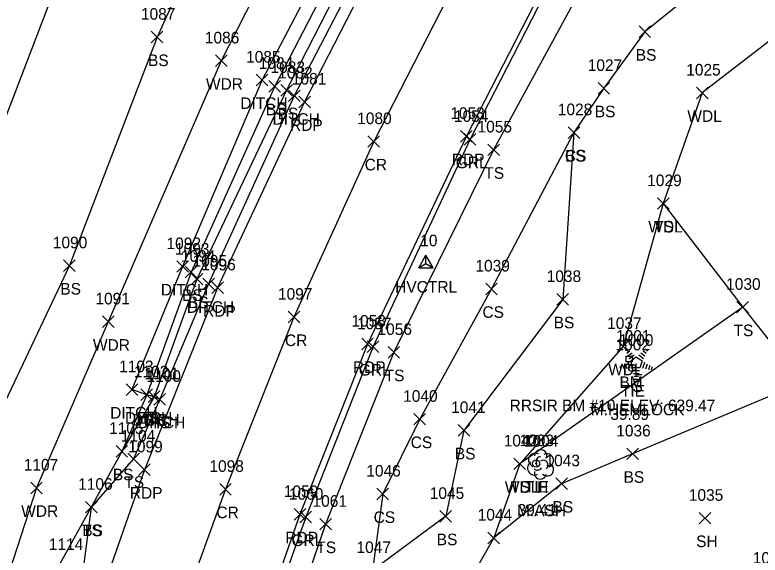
# Model space of a CAD drawing. Extents: x 1551995 to 1555700, y 777276 to 783130.
# Drawn here: x 1554918 to 1555046.7, y 778118.1 to 778211.4 of the extents above; entities that cross this region are included whole.
import ezdxf

# ---------------------------------------------------------------- set-up
doc = ezdxf.new("R2010")
doc.units = 0
for name, color, linetype in [('C_A', 7, 'Continuous'), ('C_C', 7, 'Continuous'), ('C_I', 7, 'Continuous'), ('CBP', 7, 'Continuous'), ('CPBM', 7, 'Continuous'), ('CPSM', 7, 'Continuous'), ('D_A', 7, 'Continuous'), ('D_I', 7, 'Continuous'), ('D_TIC', 7, 'Continuous'), ('DD', 7, 'Continuous'), ('L_A', 7, 'Continuous'), ('L_C', 7, 'Continuous'), ('L_I', 7, 'Continuous'), ('L_TIC', 7, 'Continuous'), ('LAWA', 7, 'Continuous'), ('LELB', 7, 'Continuous'), ('LTC', 7, 'Continuous'), ('LTD', 7, 'Continuous'), ('P_A', 7, 'Continuous'), ('P_I', 7, 'Continuous'), ('P_TIC', 7, 'Continuous'), ('PET', 7, 'Continuous'), ('PRC', 7, 'Continuous'), ('R_A', 7, 'Continuous'), ('R_I', 7, 'Continuous'), ('R_TIC', 7, 'Continuous'), ('RGR', 7, 'Continuous')]:
    doc.layers.add(name, color=color, linetype=linetype)

msp = doc.modelspace()

# ---------------------------------------------------------------- linework, layer by layer
at = {"layer": 'CBP'}
for centre, radius in [((1555024.62, 778150.43), 0.625), ((1555024.62, 778150.43), 0.0833), ((1555008.03, 778133.9), 0.625), ((1555008.03, 778133.9), 0.0833)]:
    msp.add_circle(centre, radius, dxfattribs=at)
at = {"layer": 'CPBM'}
for p, q in [((1555023.63, 778151.43), (1555023.63, 778152.43)), ((1555023.63, 778152.43), (1555024.63, 778152.43)), ((1555024.63, 778151.43), (1555023.63, 778151.43)), ((1555024.13, 778151.93), (1555024.13, 778151.93)), ((1555024.13, 778151.93), (1555024.13, 778151.93)), ((1555024.63, 778152.43), (1555024.63, 778151.43))]:
    msp.add_line(p, q, dxfattribs=at)
at = {"layer": 'CPSM'}
for p, q in [((1554987.76, 778167.69), (1554989.01, 778169.86)), ((1554987.76, 778167.69), (1554989.01, 778169.86)), ((1554987.76, 778167.69), (1554989.01, 778169.86)), ((1554987.76, 778167.69), (1554989.01, 778169.86)), ((1554987.76, 778167.69), (1554989.01, 778169.86)), ((1554987.76, 778167.69), (1554989.01, 778169.86)), ((1554987.76, 778167.69), (1554989.01, 778169.86)), ((1554990.26, 778167.69), (1554989.01, 778169.86)), ((1554989.01, 778168.41), (1554989.01, 778169.86)), ((1554990.26, 778167.69), (1554989.01, 778169.86)), ((1554989.01, 778168.41), (1554989.01, 778169.86)), ((1554990.26, 778167.69), (1554989.01, 778169.86)), ((1554989.01, 778168.41), (1554989.01, 778169.86)), ((1554990.26, 778167.69), (1554989.01, 778169.86)), ((1554989.01, 778168.41), (1554989.01, 778169.86)), ((1554990.26, 778167.69), (1554989.01, 778169.86)), ((1554989.01, 778168.41), (1554989.01, 778169.86)), ((1554990.26, 778167.69), (1554989.01, 778169.86)), ((1554989.01, 778168.41), (1554989.01, 778169.86)), ((1554990.26, 778167.69), (1554989.01, 778169.86)), ((1554989.01, 778168.41), (1554989.01, 778169.86)), ((1554987.76, 778167.69), (1554989.01, 778168.41)), ((1554987.76, 778167.69), (1554989.01, 778168.41)), ((1554987.76, 778167.69), (1554989.01, 778168.41)), ((1554987.76, 778167.69), (1554989.01, 778168.41)), ((1554987.76, 778167.69), (1554989.01, 778168.41)), ((1554987.76, 778167.69), (1554989.01, 778168.41)), ((1554987.76, 778167.69), (1554989.01, 778168.41)), ((1554989.01, 778168.41), (1554989.01, 778168.41)), ((1554989.01, 778168.41), (1554990.26, 778167.69)), ((1554989.01, 778168.41), (1554989.01, 778168.41)), ((1554989.01, 778168.41), (1554990.26, 778167.69)), ((1554989.01, 778168.41), (1554989.01, 778168.41)), ((1554989.01, 778168.41), (1554990.26, 778167.69)), ((1554989.01, 778168.41), (1554989.01, 778168.41)), ((1554989.01, 778168.41), (1554990.26, 778167.69)), ((1554989.01, 778168.41), (1554989.01, 778168.41)), ((1554989.01, 778168.41), (1554990.26, 778167.69)), ((1554989.01, 778168.41), (1554989.01, 778168.41)), ((1554989.01, 778168.41), (1554990.26, 778167.69)), ((1554989.01, 778168.41), (1554989.01, 778168.41)), ((1554989.01, 778168.41), (1554990.26, 778167.69)), ((1554987.76, 778167.69), (1554990.26, 778167.69)), ((1554987.76, 778167.69), (1554990.26, 778167.69)), ((1554987.76, 778167.69), (1554990.26, 778167.69)), ((1554987.76, 778167.69), (1554990.26, 778167.69)), ((1554987.76, 778167.69), (1554990.26, 778167.69)), ((1554987.76, 778167.69), (1554990.26, 778167.69)), ((1554987.76, 778167.69), (1554990.26, 778167.69))]:
    msp.add_line(p, q, dxfattribs=at)
at = {"layer": 'D_TIC'}
for points in [[(1554959.71, 778199.12), (1554961.71, 778201.12)], [(1554961.71, 778199.12), (1554959.71, 778201.12)], [(1554965.26, 778196.38), (1554967.26, 778198.38)], [(1554967.26, 778196.38), (1554965.26, 778198.38)], [(1554945.97, 778166.91), (1554947.97, 778168.91)], [(1554947.97, 778166.91), (1554945.97, 778168.91)], [(1554950.47, 778163.91), (1554952.47, 778165.91)], [(1554952.47, 778163.91), (1554950.47, 778165.91)], [(1554937.22, 778145.67), (1554939.22, 778147.67)], [(1554939.22, 778145.67), (1554937.22, 778147.67)], [(1554937.22, 778145.67), (1554939.22, 778147.67)], [(1554939.22, 778145.67), (1554937.22, 778147.67)], [(1554939.77, 778144.78), (1554941.77, 778146.78)], [(1554941.77, 778144.78), (1554939.77, 778146.78)], [(1554941.04, 778144.43), (1554943.04, 778146.43)], [(1554943.04, 778144.43), (1554941.04, 778146.43)], [(1554942.03, 778144), (1554944.03, 778146)], [(1554944.03, 778144), (1554942.03, 778146)]]:
    msp.add_lwpolyline(points, dxfattribs=at)
at = {"layer": 'DD'}
for points in [[(1555007.77, 778290.58), (1554983.94, 778244.46), (1554960.71, 778200.12), (1554946.97, 778167.91), (1554938.22, 778146.67)], [(1555014.72, 778285.98), (1554988.93, 778241.04), (1554966.26, 778197.38), (1554951.47, 778164.91), (1554943.03, 778145), (1554942.04, 778145.43), (1554940.77, 778145.78), (1554938.22, 778146.67)]]:
    msp.add_lwpolyline(points, dxfattribs=at)
at = {"layer": 'L_TIC'}
for points in [[(1555025.82, 778207.44), (1555027.82, 778209.44)], [(1555027.82, 778207.44), (1555025.82, 778209.44)], [(1554941.56, 778206.52), (1554943.56, 778208.52)], [(1554943.56, 778206.52), (1554941.56, 778208.52)], [(1554952.65, 778202.43), (1554954.65, 778204.43)], [(1554954.65, 778202.43), (1554952.65, 778204.43)], [(1554961.9, 778198.03), (1554963.9, 778200.03)], [(1554963.9, 778198.03), (1554961.9, 778200.03)], [(1554963.94, 778197.34), (1554965.94, 778199.34)], [(1554965.94, 778197.34), (1554963.94, 778199.34)], [(1555018.74, 778197.68), (1555020.74, 778199.68)], [(1555020.74, 778197.68), (1555018.74, 778199.68)], [(1555035.75, 778196.89), (1555037.75, 778198.89)], [(1555037.75, 778196.89), (1555035.75, 778198.89)], [(1555013.58, 778190.04), (1555015.58, 778192.04)], [(1555015.58, 778190.04), (1555013.58, 778192.04)], [(1555013.58, 778190.04), (1555015.58, 778192.04)], [(1555015.58, 778190.04), (1555013.58, 778192.04)], [(1554999.7, 778187.06), (1555001.7, 778189.06)], [(1555001.7, 778187.06), (1554999.7, 778189.06)], [(1555029.02, 778177.79), (1555031.02, 778179.79)], [(1555031.02, 778177.79), (1555029.02, 778179.79)], [(1555029.02, 778177.79), (1555031.02, 778179.79)], [(1555031.02, 778177.79), (1555029.02, 778179.79)], [(1554926.41, 778167.06), (1554928.41, 778169.06)], [(1554928.41, 778167.06), (1554926.41, 778169.06)], [(1554947.43, 778165.96), (1554949.43, 778167.96)], [(1554949.43, 778165.96), (1554947.43, 778167.96)], [(1554948.46, 778164.73), (1554950.46, 778166.73)], [(1554950.46, 778164.73), (1554948.46, 778166.73)], [(1554999.34, 778163.05), (1555001.34, 778165.05)], [(1555001.34, 778163.05), (1554999.34, 778165.05)], [(1555011.64, 778161.24), (1555013.64, 778163.24)], [(1555013.64, 778161.24), (1555011.64, 778163.24)], [(1555042.74, 778159.89), (1555044.74, 778161.89)], [(1555044.74, 778159.89), (1555042.74, 778161.89)], [(1555042.74, 778159.89), (1555044.74, 778161.89)], [(1555044.74, 778159.89), (1555042.74, 778161.89)], [(1554933.13, 778157.37), (1554935.13, 778159.37)], [(1554935.13, 778157.37), (1554933.13, 778159.37)], [(1554982.47, 778152.1), (1554984.47, 778154.1)], [(1554984.47, 778152.1), (1554982.47, 778154.1)], [(1555022.09, 778153.13), (1555024.09, 778155.13)], [(1555024.09, 778153.13), (1555022.09, 778155.13)], [(1554939.77, 778144.78), (1554941.77, 778146.78)], [(1554941.77, 778144.78), (1554939.77, 778146.78)], [(1554941.04, 778144.43), (1554943.04, 778146.43)], [(1554943.04, 778144.43), (1554941.04, 778146.43)], [(1554942.03, 778144), (1554944.03, 778146)], [(1554944.03, 778144), (1554942.03, 778146)], [(1554986.94, 778140.56), (1554988.94, 778142.56)], [(1554988.94, 778140.56), (1554986.94, 778142.56)], [(1554994.57, 778138.61), (1554996.57, 778140.61)], [(1554996.57, 778138.61), (1554994.57, 778140.61)], [(1554935.48, 778135), (1554937.48, 778137)], [(1554937.48, 778135), (1554935.48, 778137)], [(1554935.48, 778135), (1554937.48, 778137)], [(1554937.48, 778135), (1554935.48, 778137)], [(1555023.71, 778134.57), (1555025.71, 778136.57)], [(1555025.71, 778134.57), (1555023.71, 778136.57)], [(1554937.52, 778133.69), (1554939.52, 778135.69)], [(1554939.52, 778133.69), (1554937.52, 778135.69)], [(1555004.22, 778132.85), (1555006.22, 778134.85)], [(1555006.22, 778132.85), (1555004.22, 778134.85)], [(1555004.22, 778132.85), (1555006.22, 778134.85)], [(1555006.22, 778132.85), (1555004.22, 778134.85)], [(1554920.74, 778128.69), (1554922.74, 778130.69)], [(1554922.74, 778128.69), (1554920.74, 778130.69)], [(1555011.44, 778129.42), (1555013.44, 778131.42)], [(1555013.44, 778129.42), (1555011.44, 778131.42)], [(1554980.54, 778127.64), (1554982.54, 778129.64)], [(1554982.54, 778127.64), (1554980.54, 778129.64)], [(1554930.2, 778125.36), (1554932.2, 778127.36)], [(1554932.2, 778125.36), (1554930.2, 778127.36)], [(1554930.2, 778125.36), (1554932.2, 778127.36)], [(1554932.2, 778125.36), (1554930.2, 778127.36)], [(1554991.44, 778123.79), (1554993.44, 778125.79)], [(1554993.44, 778123.79), (1554991.44, 778125.79)], [(1554970.68, 778122.43), (1554972.68, 778124.43)], [(1554972.68, 778122.43), (1554970.68, 778124.43)], [(1555036.21, 778123.47), (1555038.21, 778125.47)], [(1555038.21, 778123.47), (1555036.21, 778125.47)], [(1554999.72, 778120.06), (1555001.72, 778122.06)], [(1555001.72, 778120.06), (1554999.72, 778122.06)], [(1554999.72, 778120.06), (1555001.72, 778122.06)], [(1555001.72, 778120.06), (1554999.72, 778122.06)]]:
    msp.add_lwpolyline(points, dxfattribs=at)
at = {"layer": 'LAWA'}
for points in [[(1555000.96, 778294.87), (1554977.33, 778249.83), (1554953.65, 778203.43), (1554934.13, 778158.37), (1554921.74, 778129.69), (1554915, 778109.12), (1554905.48, 778082.18), (1554899.62, 778064.01), (1554889.87, 778042.09), (1554882.71, 778000.01), (1554871.69, 777971.47), (1554868.37, 777961.54), (1554861.96, 777920.45), (1554858.53, 777878.75), (1554855.37, 777850.35), (1554848.67, 777827.4), (1554836.72, 777779.63)], [(1555085.12, 778246.6), (1555062.11, 778217.51), (1555036.75, 778197.89), (1555030.02, 778178.79), (1555023.09, 778154.13), (1555005.22, 778133.85), (1555000.72, 778121.06), (1554983.85, 778091.44), (1554975.19, 778092.03), (1554970.99, 778074.93), (1554967.22, 778059.88), (1554967.17, 778023.98), (1554956.28, 777979.25), (1554949.24, 777950.5), (1554942.15, 777917.97), (1554937.88, 777884.35), (1554924.17, 777845.95), (1554911.99, 777797.39)]]:
    msp.add_lwpolyline(points, dxfattribs=at)
at = {"layer": 'LELB'}
for points in [[(1554968.28, 778312.04), (1554950, 778266.53), (1554926.49, 778220.19), (1554908.96, 778174.42), (1554896.48, 778148.26), (1554883.58, 778119.09), (1554877.33, 778100.58), (1554861.43, 778063.06), (1554849.04, 778068.43), (1554838.51, 778079.97)], [(1554991.44, 778299.23), (1554965.18, 778257.46), (1554942.56, 778207.52), (1554927.41, 778168.06), (1554913.27, 778138.26), (1554902.03, 778109.91)], [(1555010.39, 778288.8), (1554986.01, 778243.63), (1554962.9, 778199.03), (1554948.43, 778166.96), (1554940.77, 778145.78), (1554936.48, 778136)], [(1555012.41, 778287.51), (1554987.42, 778242.35), (1554964.94, 778198.34), (1554949.46, 778165.73), (1554942.04, 778145.43), (1554936.48, 778136), (1554931.2, 778126.36), (1554925.41, 778115.96), (1554925.69, 778108.05), (1554919.03, 778090.31), (1554918.44, 778089.95), (1554914.24, 778077.2), (1554901.57, 778039.07), (1554894.39, 777997.12), (1554883.88, 777962.74), (1554876.08, 777918.21), (1554866.8, 777876.47), (1554857.76, 777827.38), (1554846.36, 777775.83)], [(1555043.36, 778265.96), (1555018.33, 778220.45), (1555000.7, 778188.06), (1554983.47, 778153.1), (1554971.68, 778123.43), (1554963.77, 778100.46)], [(1555062.53, 778257.03), (1555043.05, 778221.53), (1555026.82, 778208.44), (1555019.74, 778198.68), (1555014.58, 778191.04), (1555012.64, 778162.24), (1554995.57, 778139.61), (1554992.44, 778124.79), (1554979.79, 778115.45), (1554974.95, 778099.31), (1554975.19, 778092.03)], [(1555014.58, 778191.04), (1555000.34, 778164.05), (1554987.94, 778141.56), (1554981.54, 778128.64), (1554979.79, 778115.45)], [(1555030.02, 778178.79), (1555043.74, 778160.89), (1555054.04, 778147.86), (1555060.5, 778139.33), (1555048.25, 778113.6), (1555032.66, 778099.46), (1555025.51, 778075.72)], [(1555043.74, 778160.89), (1555005.22, 778133.85)], [(1555054.04, 778147.86), (1555024.71, 778135.57), (1555012.44, 778130.42), (1555000.72, 778121.06)], [(1554943.03, 778145), (1554938.52, 778134.69), (1554931.2, 778126.36), (1554928.67, 778106.77)]]:
    msp.add_lwpolyline(points, dxfattribs=at)
at = {"layer": 'LTC'}
for p, q in [((1555023.49, 778153.44), (1555023.84, 778153.7)), ((1555023.7, 778152.98), (1555024.23, 778153.36)), ((1555023.91, 778152.51), (1555024.61, 778153.02)), ((1555024.12, 778152.04), (1555025, 778152.68)), ((1555025.77, 778152.64), (1555026.58, 778152.05)), ((1555026.14, 778152.99), (1555026.82, 778152.49)), ((1555026.52, 778153.33), (1555027.06, 778152.93)), ((1555026.89, 778153.68), (1555027.31, 778153.38)), ((1555023.89, 778151.37), (1555024.22, 778150.35)), ((1555024.34, 778151.59), (1555025.35, 778152.32)), ((1555024.34, 778151.59), (1555024.73, 778150.4)), ((1555025.35, 778152.32), (1555026.35, 778151.6)), ((1555026.35, 778151.6), (1555025.96, 778150.4)), ((1555026.79, 778151.33), (1555026.45, 778150.29)), ((1555022.52, 778150.72), (1555022.67, 778150.25)), ((1555022.98, 778150.94), (1555023.19, 778150.29)), ((1555023.43, 778151.15), (1555023.7, 778150.32)), ((1555025.96, 778150.4), (1555024.73, 778150.4)), ((1555027.23, 778151.08), (1555026.94, 778150.19)), ((1555027.68, 778150.83), (1555027.44, 778150.1)), ((1555028.12, 778150.58), (1555027.93, 778150)), ((1555025.92, 778149.9), (1555024.78, 778149.9)), ((1555025.84, 778149.4), (1555024.85, 778149.4)), ((1555025.75, 778148.9), (1555024.92, 778148.9)), ((1555025.67, 778148.4), (1555024.99, 778148.4))]:
    msp.add_line(p, q, dxfattribs=at)
at = {"layer": 'LTD'}
msp.add_line((1555008.79, 778133.8), (1555008.79, 778133.8), dxfattribs=at)
msp.add_line((1555008.79, 778133.8), (1555008.79, 778133.8), dxfattribs=at)
msp.add_arc((1555008.84, 778135.24), 1.05, 335.5272, 180.9563, dxfattribs=at)
for centre, major_axis, ratio, start_param, end_param in [((1555008, 778134.47), (1.21, -0.51), 0.895232, 1.570796, 4.712389), ((1555008.58, 778134.26), (-0.208, -0.792), 0.645439, 3.141593, 6.283185), ((1555009.29, 778133.64), (-0.5, 0.667), 0.989748, 3.141593, 6.283185), ((1555009.83, 778134.39), (-1.14, -0.48), 0.949671, 1.570796, 4.712389), ((1555007.71, 778133.09), (0.58, -1.04), 0.959034, 3.141593, 6.283185), ((1555009.79, 778132.97), (-1.09, 0.79), 0.841452, 1.570796, 4.712389), ((1555008.79, 778132.3), (0.26, 1.06), 0.942809, 1.570796, 4.712389), ((1555008.33, 778133.05), (-0.625, -0.083), 0.423636, 0, 3.141593)]:
    msp.add_ellipse(centre, major_axis=major_axis, ratio=ratio, start_param=start_param, end_param=end_param, dxfattribs=at)
at = {"layer": 'P_TIC'}
for points in [[(1554967.05, 778195.33), (1554969.05, 778197.33)], [(1554969.05, 778195.33), (1554967.05, 778197.33)], [(1554995, 778189.4), (1554997, 778191.4)], [(1554997, 778189.4), (1554995, 778191.4)], [(1554979, 778188.5), (1554981, 778190.5)], [(1554981, 778188.5), (1554979, 778190.5)], [(1554952.03, 778163.25), (1554954.03, 778165.25)], [(1554954.03, 778163.25), (1554952.03, 778165.25)], [(1554965.22, 778158.18), (1554967.22, 778160.18)], [(1554967.22, 778158.18), (1554965.22, 778160.18)], [(1554977.91, 778153.53), (1554979.91, 778155.53)], [(1554979.91, 778153.53), (1554977.91, 778155.53)], [(1554939.37, 778131.83), (1554941.37, 778133.83)], [(1554941.37, 778131.83), (1554939.37, 778133.83)], [(1554953.38, 778128.46), (1554955.38, 778130.46)], [(1554955.38, 778128.46), (1554953.38, 778130.46)], [(1554966.24, 778124.11), (1554968.24, 778126.11)], [(1554968.24, 778124.11), (1554966.24, 778126.11)]]:
    msp.add_lwpolyline(points, dxfattribs=at)
at = {"layer": 'PET'}
for points in [[(1555086.85, 778385.99), (1555058.53, 778347.95), (1555034.13, 778312.76), (1555016.69, 778284.76), (1554990.68, 778240.38), (1554968.05, 778196.33), (1554953.03, 778164.25), (1554940.37, 778132.83), (1554930.99, 778106.02), (1554923.77, 778083.63), (1554909.85, 778036.75), (1554900.04, 777995.37), (1554891.67, 777961.45), (1554881.9, 777917.03), (1554872.92, 777875.28), (1554862.74, 777826.66), (1554851.19, 777774.32)], [(1555108.52, 778369.81), (1555078.86, 778330.23), (1555056.92, 778298.28), (1555038.33, 778268.72), (1555013, 778223.52), (1554996, 778190.4), (1554978.91, 778154.53), (1554967.24, 778125.11), (1554957.25, 778096.67), (1554950.17, 778073.38), (1554937.06, 778028.22), (1554926.8, 777988.52), (1554918.72, 777954.59), (1554908.46, 777910.08), (1554899.75, 777869.14), (1554889.9, 777822.39), (1554877.4, 777767.74)]]:
    msp.add_lwpolyline(points, dxfattribs=at)
at = {"layer": 'PRC'}
msp.add_lwpolyline([(1555098.33, 778377.48), (1555069.71, 778339.49), (1555045.49, 778304.7), (1555028.73, 778278.05), (1555002.89, 778234.08), (1554980, 778189.5), (1554966.22, 778159.18), (1554954.38, 778129.46), (1554944.07, 778101.03), (1554941.59, 778092.54), (1554937.34, 778078.77), (1554924.27, 778032.77), (1554914.16, 777991.62), (1554905.84, 777957.86), (1554895.98, 777913.96), (1554886.88, 777872.59), (1554876.72, 777824.26), (1554864.6, 777770.35)], dxfattribs=at)
at = {"layer": 'R_TIC'}
for points in [[(1554995.63, 778188.88), (1554997.63, 778190.88)], [(1554997.63, 778188.88), (1554995.63, 778190.88)], [(1554978.88, 778153.08), (1554980.88, 778155.08)], [(1554980.88, 778153.08), (1554978.88, 778155.08)], [(1554967.24, 778123.65), (1554969.24, 778125.65)], [(1554969.24, 778123.65), (1554967.24, 778125.65)]]:
    msp.add_lwpolyline(points, dxfattribs=at)
at = {"layer": 'RGR'}
msp.add_lwpolyline([(1555039.56, 778268.3), (1555013.62, 778223), (1554996.63, 778189.88), (1554979.88, 778154.08), (1554968.24, 778124.65), (1554958.2, 778096.32), (1554950.97, 778072.94), (1554937.27, 778027.95), (1554927.65, 777988.1), (1554919.66, 777954.37), (1554909.72, 777910.11), (1554900.5, 777868.18), (1554890.69, 777822.54), (1554878.36, 777767.59), (1554870.52, 777731.32), (1554860.9, 777689.38), (1554849.55, 777645.14), (1554835.81, 777600.33), (1554822.79, 777564.15), (1554817.07, 777548.72), (1554816.7, 777536.06)], dxfattribs=at)

# ---------------------------------------------------------------- texts
at = {"layer": 'C_A'}
for s, p in [('HVCTRL', (1554983.7, 778163.41)), ('HVCTRL', (1554983.7, 778163.41)), ('HVCTRL', (1554983.7, 778163.41)), ('HVCTRL', (1554983.7, 778163.41)), ('HVCTRL', (1554983.7, 778163.41)), ('HVCTRL', (1554983.7, 778163.41)), ('HVCTRL', (1554983.7, 778163.41)), ('BM', (1555022.45, 778146.93)), ('TIE', (1555022.7, 778145.43)), ('TIE', (1555006.11, 778128.9))]:
    msp.add_text(s, height=2, dxfattribs=at).set_placement(p)
at = {"layer": 'C_C'}
for s, p in [('RRSIR BM #10 ELEV: 639.47', (1555003.47, 778142.93)), ('39.89', (1555020.86, 778141.43)), ('39.41', (1555004.85, 778124.9))]:
    msp.add_text(s, height=2, dxfattribs=at).set_placement(p)
at = {"layer": 'C_I'}
for s, p in [('10', (1554988.03, 778171.41)), ('10', (1554988.03, 778171.41)), ('10', (1554988.03, 778171.41)), ('10', (1554988.03, 778171.41)), ('10', (1554988.03, 778171.41)), ('10', (1554988.03, 778171.41)), ('10', (1554988.03, 778171.41)), ('1001', (1555021.85, 778154.93)), ('1002', (1555021.77, 778153.43)), ('1003', (1555005.18, 778136.9))]:
    msp.add_text(s, height=2, dxfattribs=at).set_placement(p)
at = {"layer": 'D_A'}
for p in [(1554956.94, 778195.12), (1554962.5, 778192.38), (1554943.21, 778162.91), (1554947.71, 778159.91), (1554934.46, 778141.67), (1554934.46, 778141.67), (1554937.01, 778140.78), (1554938.28, 778140.43), (1554939.26, 778140)]:
    msp.add_text('DITCH', height=2, dxfattribs=at).set_placement(p)
at = {"layer": 'D_I'}
for s, p in [('1085', (1554957.94, 778203.12)), ('1082', (1554963.49, 778200.38)), ('1092', (1554944.2, 778170.91)), ('1095', (1554948.7, 778167.91)), ('1103', (1554936.01, 778149.67)), ('1103', (1554936.01, 778149.67)), ('1102', (1554938.57, 778148.78)), ('1101', (1554940.4, 778148.43)), ('1100', (1554940.73, 778148))]:
    msp.add_text(s, height=2, dxfattribs=at).set_placement(p)
at = {"layer": 'L_A'}
for s, p in [('BS', (1555025.26, 778203.44)), ('BS', (1554941, 778202.52)), ('WDR', (1554951.01, 778198.43)), ('BS', (1554961.34, 778194.03)), ('BS', (1554963.39, 778193.34)), ('BS', (1555018.18, 778193.68)), ('WDL', (1555034.17, 778192.89)), ('CS', (1555013.02, 778186.04)), ('BS', (1555013.02, 778186.04)), ('TS', (1554999.11, 778183.06)), ('WDL', (1555027.43, 778173.79)), ('TS', (1555028.43, 778173.79)), ('BS', (1554925.85, 778163.06)), ('BS', (1554946.87, 778161.96)), ('BS', (1554947.9, 778160.73)), ('CS', (1554998.78, 778159.05)), ('BS', (1555011.08, 778157.24)), ('TS', (1555042.15, 778155.89)), ('TS', (1555042.15, 778155.89)), ('WDR', (1554931.49, 778153.37)), ('TS', (1554981.88, 778148.1)), ('WDL', (1555020.51, 778149.13)), ('S', (1555024.68, 778146.23)), ('BS', (1554939.22, 778140.78)), ('BS', (1554940.48, 778140.43)), ('TS', (1554941.44, 778140)), ('CS', (1554986.38, 778136.56)), ('BS', (1554994.01, 778134.61)), ('BS', (1554934.92, 778131)), ('BS', (1554934.92, 778131)), ('BS', (1555023.15, 778130.57)), ('TS', (1554936.92, 778129.69)), ('WDL', (1555002.64, 778128.85)), ('TS', (1555003.63, 778128.85)), ('H', (1555008.22, 778128.8)), ('BS', (1555010.88, 778125.42)), ('WDR', (1554919.1, 778124.69)), ('CS', (1554979.98, 778123.64)), ('TS', (1554929.61, 778121.36)), ('BS', (1554929.64, 778121.36)), ('BS', (1554990.88, 778119.79)), ('TS', (1554970.08, 778118.43)), ('SH', (1555035.69, 778119.47))]:
    msp.add_text(s, height=2, dxfattribs=at).set_placement(p)
at = {"layer": 'L_C'}
for s, p in [('M.HEMLOCK', (1555017.48, 778142.23)), ('M.ASH', (1555004.74, 778124.8))]:
    msp.add_text(s, height=2, dxfattribs=at).set_placement(p)
at = {"layer": 'L_I'}
for s, p in [('1087', (1554939.78, 778210.52)), ('1086', (1554950.82, 778206.43)), ('1084', (1554960.13, 778202.03)), ('1083', (1554962.17, 778201.34)), ('1027', (1555016.97, 778201.68)), ('1025', (1555033.98, 778200.89)), ('1028', (1555011.8, 778194.04)), ('1028', (1555011.8, 778194.04)), ('1055', (1554997.93, 778191.06)), ('1029', (1555027.24, 778181.79)), ('1029', (1555027.24, 778181.79)), ('1090', (1554924.56, 778171.06)), ('1093', (1554945.66, 778169.96)), ('1094', (1554946.69, 778168.73)), ('1039', (1554997.56, 778167.05)), ('1038', (1555009.87, 778165.24)), ('1030', (1555040.88, 778163.89)), ('1030', (1555040.88, 778163.89)), ('1091', (1554931.92, 778161.37)), ('1037', (1555020.32, 778157.13)), ('1056', (1554980.65, 778156.1)), ('1000', (1555022.36, 778154.23)), ('1102', (1554938.57, 778148.78)), ('1101', (1554940.4, 778148.43)), ('1100', (1554940.73, 778148)), ('1040', (1554985.08, 778144.56)), ('1041', (1554993.37, 778142.61)), ('1105', (1554934.27, 778139)), ('1105', (1554934.27, 778139)), ('1104', (1554936.31, 778137.69)), ('1036', (1555021.89, 778138.57)), ('1042', (1555002.45, 778136.85)), ('1042', (1555002.45, 778136.85)), ('1004', (1555005.94, 778136.8)), ('1107', (1554919.53, 778132.69)), ('1043', (1555009.67, 778133.42)), ('1046', (1554978.71, 778131.64)), ('1106', (1554928.94, 778129.36)), ('1106', (1554928.94, 778129.36)), ('1045', (1554989.67, 778127.79)), ('1035', (1555034.43, 778127.47)), ('1061', (1554969.42, 778126.43)), ('1044', (1554997.95, 778124.06)), ('1044', (1554997.95, 778124.06)), ('1114', (1554923.86, 778118.96)), ('1114', (1554923.86, 778118.96)), ('1047', (1554977.02, 778118.45)), ('1047', (1554977.02, 778118.45)), ('1034', (1555045.48, 778116.6))]:
    msp.add_text(s, height=2, dxfattribs=at).set_placement(p)
at = {"layer": 'LTC'}
msp.add_text('.', height=1.04, rotation=270, dxfattribs=at).set_placement((1555025.24, 778151.34))
at = {"layer": 'P_A'}
for s, p in [('RDP', (1554965.54, 778191.33)), ('RDP', (1554993.49, 778185.4)), ('CR', (1554978.43, 778184.5)), ('RDP', (1554950.52, 778159.25)), ('CR', (1554964.66, 778154.18)), ('RDP', (1554976.4, 778149.53)), ('RDP', (1554937.86, 778127.83)), ('CR', (1554952.82, 778124.46)), ('RDP', (1554964.72, 778120.11))]:
    msp.add_text(s, height=2, dxfattribs=at).set_placement(p)
at = {"layer": 'P_I'}
for s, p in [('1081', (1554965.85, 778199.33)), ('1053', (1554993.23, 778193.4)), ('1080', (1554977.14, 778192.5)), ('1096', (1554950.2, 778167.25)), ('1097', (1554963.45, 778162.18)), ('1058', (1554976.14, 778157.53)), ('1099', (1554937.59, 778135.83)), ('1098', (1554951.61, 778132.46)), ('1059', (1554964.46, 778128.11))]:
    msp.add_text(s, height=2, dxfattribs=at).set_placement(p)
at = {"layer": 'R_A'}
for p in [(1554994.17, 778184.88), (1554977.42, 778149.08), (1554965.79, 778119.65)]:
    msp.add_text('GRL', height=2, dxfattribs=at).set_placement(p)
at = {"layer": 'R_I'}
for s, p in [('1054', (1554993.85, 778192.88)), ('1057', (1554977.11, 778157.08)), ('1060', (1554965.34, 778127.65))]:
    msp.add_text(s, height=2, dxfattribs=at).set_placement(p)

doc.saveas('drawing.dxf')
